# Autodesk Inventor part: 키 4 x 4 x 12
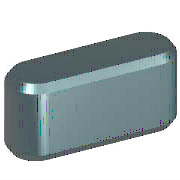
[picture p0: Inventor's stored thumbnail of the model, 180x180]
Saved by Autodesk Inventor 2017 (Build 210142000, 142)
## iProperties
IsCustomPart: 1
Created: 2012-02
Part Number: 키 4 x 4 x 12
Material: 강철, 연강
Description: 키 및 해당 키홈
Document SubType Name: Modeling
Standard: KS B 1311
Designer: mduedu
Standards Organization: KS
Language: ko-KR
Size Designation: 4 x 4 x 12
Categories: <MemberInstance><Categories><Category DisplayName="샤프트 부품" InternalName="7f7aeb1f-a693-4053-b835-cee3144e0d98" Mnemonic="SHFT"><Category DisplayName="키" Interna
Density: 7.86 g/cm^3
Mass: 1.38739 g
Surface Area: 1.94869 cm^2
Volume: 0.176513 cm^3
Appearance: 노란색
Author: mduedu
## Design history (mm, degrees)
workplane "Work Plane1"
workplane "Work Plane2"
sketch "스케치1"
  geometry: L1 (2, 2)-(10, 2); L2 (10, -2)-(2, -2); L3 (0, 9.4)-(0, -7.4) reference; L4 (-5, 0)-(30, 0) reference; L5 (12, 0)-(12, 7); A1 r 2 centre (2, 0) between (2, 2) and (2, -2); A2 r 2 centre (10, 0) between (10, -2) and (10, 2)
  constraints: 6 end point, 5 point on circle, 4 tangent, 3 point on line, 2 centre point, 1 horizontal, 1 parallel, 1 perpendicular
  dimensions: "d0" = 2 radius of A1 (= 0.5 x PB); "d13" = 2 radius of A2 (= 0.5 x PB); "d14" = 12 distance between parallel lines of L5 L3 (= NLG)
extrude "본체1" new body sketch "스케치1" taper "d3" = 0 deg; stored distance "d4" = 10
workplane "Work Plane3"
body "Solid1"
chamfer "모따기1" distance "d8" = 0.25 (= PHH); stored, may be unused: second distance "d9" = 0.25 (= PHH), angle "d15" = 45 deg
other parameters: "d1" = -2.5 (= -PNT), "d2" = 1.5 (= PH - PNT), "NLG" = 12 [user parameter; used in 3 equation terms], "PB" = 4 [user parameter; used in 2 equation terms], "PNT" = 2.5 [user parameter; used in 2 equation terms], "PH" = 4 [user parameter; used in 1 equation term], "PHH" = 0.25 [user parameter; used in 2 equation terms], "d10" = 0, "d16" = 0, "d17" = 0, "d18" = 0, "PLB2" = 12 (= NLG) [user parameter], "WDMAX" = 12 [user parameter], "PLB1" = 12 (= NLG) [user parameter], "RR" = 0.08 [user parameter], "PUEB" = 1.8 [user parameter]
